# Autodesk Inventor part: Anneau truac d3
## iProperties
Author: Flavien MARTY
Shininess: 86.0
PropertySet Name: _Private Model Information
Created: 2001-10
Part Number: Anneau truac d3
Material: Par défaut
Document SubType Name: Modélisation
Designer: Flavien MARTY
Control State: 0
Master: False
Checked Out: False
PropertySet Name: Design Tracking Control
Density: 0.0
Volumn: 0.0
Area: 0.0
PropertySet Name: Model Information
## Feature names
1. Base1
